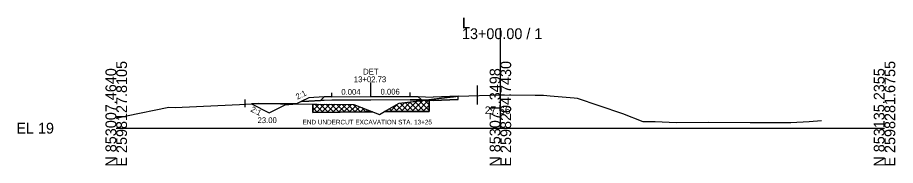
# Model space of a CAD drawing. Extents: x -26 to 1203, y -10 to 9526.
# Drawn here: x -25.7 to 202.8, y 2990.3 to 3028.8 of the extents above; entities that cross this region are included whole.
import ezdxf

# ---------------------------------------------------------------- set-up
doc = ezdxf.new("R2010")
doc.units = 0
for name, color, linetype in [('Exist Cross Section Cell', 7, 'Continuous'), ('Exist XS Center Line Elevation Label', 7, 'Continuous'), ('Exist XS Ground Line', 7, 'Continuous'), ('Prop XS Alignment Label', 7, 'Continuous'), ('Prop XS DDE', 7, 'Continuous'), ('Prop XS DDE Earthwork Shape', 7, 'Continuous'), ('Prop XS DDE Elevations', 7, 'Continuous'), ('Prop XS DDE Slope Text', 7, 'Continuous'), ('Prop XS Earthwork Shape', 7, 'Continuous'), ('Prop XS EOT Tick Mark', 7, 'Continuous'), ('Prop XS Exc Vertical Line 1', 7, 'Continuous'), ('Prop XS Exc Vertical Line 2', 7, 'Continuous'), ('Prop XS Finish Grade', 7, 'Continuous'), ('Prop XS Finish Grade Earthwork', 7, 'Continuous'), ('Prop XS Finish Grade Paved Shoulder', 7, 'Continuous'), ('Prop XS Finish Grade Pavement', 7, 'Continuous'), ('Prop XS Pvmt Edge Slope', 7, 'Continuous'), ('Prop XS SE Text', 7, 'Continuous'), ('Prop XS Side Slope Text', 7, 'Continuous'), ('Prop XS Station Labels', 7, 'Continuous'), ('Prop XS Subgrade Earthwork', 7, 'Continuous'), ('Prop XS Undercut Exc', 7, 'Continuous'), ('Prop XS Undercut Exc Hatch', 7, 'Continuous'), ('Scratch_Level_1', 7, 'Continuous')]:
    doc.layers.add(name, color=color, linetype=linetype)

msp = doc.modelspace()

# ---------------------------------------------------------------- linework, layer by layer
at = {"layer": 'Exist Cross Section Cell'}
for p, q in [((100, 3000), (100, 3025.98)), ((0, 3000), (100, 3000)), ((100, 3000), (200, 3000))]:
    msp.add_line(p, q, dxfattribs=at)
at = {"layer": 'Exist XS Ground Line'}
for p, q in [((73.62, 3006.47), (86.15, 3007.96)), ((86.15, 3007.96), (87.75, 3008.15)), ((87.75, 3008.15), (89.02, 3008.31)), ((89.02, 3008.31), (100.04, 3008.66)), ((100.04, 3008.66), (101.05, 3008.65)), ((101.05, 3008.65), (109.05, 3008.59)), ((109.05, 3008.59), (111.19, 3008.56)), ((111.19, 3008.56), (112.93, 3008.44)), ((112.93, 3008.44), (119.17, 3007.88)), ((119.17, 3007.88), (119.98, 3007.8)), ((119.98, 3007.8), (125.64, 3005.89)), ((2.69, 3003.22), (13.66, 3005.51)), ((13.66, 3005.51), (15.37, 3005.41)), ((15.37, 3005.41), (26.45, 3005.94)), ((26.45, 3005.94), (32.12, 3006.18)), ((32.12, 3006.18), (37.09, 3006.4)), ((37.09, 3006.4), (42.78, 3006.36)), ((42.78, 3006.36), (61.85, 3006.15)), ((61.85, 3006.15), (65.4, 3004.76)), ((69.41, 3004.04), (73.62, 3006.47)), ((125.64, 3005.89), (131.81, 3003.78)), ((0, 3002.63), (2.69, 3003.22)), ((65.4, 3004.76), (68.54, 3003.58)), ((68.54, 3003.58), (69.41, 3004.04)), ((131.81, 3003.78), (137.1, 3001.72)), ((137.1, 3001.72), (140.33, 3001.73)), ((140.33, 3001.73), (145.8, 3001.51)), ((145.8, 3001.51), (154.14, 3001.55)), ((154.14, 3001.55), (164.99, 3001.51)), ((164.99, 3001.51), (175.64, 3001.5)), ((175.64, 3001.5), (180.41, 3001.76)), ((180.41, 3001.76), (183.57, 3002))]:
    msp.add_line(p, q, dxfattribs=at)
at = {"layer": 'Prop XS DDE'}
for p, q in [((35.18, 3006.32), (39.81, 3004)), ((39.81, 3004), (43.94, 3006.06)), ((43.94, 3006.06), (46.94, 3006.31))]:
    msp.add_line(p, q, dxfattribs=at)
at = {"layer": 'Prop XS DDE Earthwork Shape'}
for p, q in [((37.09, 3006.4), (35.18, 3006.32)), ((35.18, 3006.32), (39.81, 3004)), ((42.78, 3006.36), (37.09, 3006.4)), ((39.81, 3004), (43.94, 3006.06)), ((46.94, 3006.31), (42.78, 3006.36)), ((43.94, 3006.06), (46.94, 3006.31))]:
    msp.add_line(p, q, dxfattribs=at)
at = {"layer": 'Prop XS Earthwork Shape'}
for points in [[(81.42, 3007.27), (82.51, 3007.21), (89.02, 3007.45), (89.02, 3008.31), (87.75, 3008.15), (86.15, 3007.96), (80.68, 3007.31)], [(69.87, 3004.3), (73.62, 3006.47), (80.68, 3007.31), (79.42, 3007.37), (78.51, 3007.37), (76.51, 3007.36), (66.3, 3007.29), (56.11, 3007.25), (54.11, 3007.24), (53.19, 3007.24), (50.11, 3007.04), (48.13, 3006.91), (46.94, 3006.31), (51.16, 3006.27), (61.85, 3006.15), (65.4, 3004.76), (66.69, 3004.28), (68.54, 3003.58), (69.41, 3004.04)], [(61.85, 3006.15), (65.4, 3004.76), (66.69, 3004.28), (65.4, 3004.29), (51.16, 3004.11), (51.16, 3006.27)], [(69.87, 3004.3), (73.62, 3006.47), (80.68, 3007.31), (81.42, 3007.27), (81.42, 3004.37), (70.25, 3004.32)]]:
    msp.add_lwpolyline(points, close=True, dxfattribs=at)
at = {"layer": 'Prop XS EOT Tick Mark'}
for p, q in [((56.11, 3008.17), (56.11, 3009.17)), ((76.51, 3008.27), (76.51, 3009.27))]:
    msp.add_line(p, q, dxfattribs=at)
at = {"layer": 'Prop XS Exc Vertical Line 1'}
msp.add_line((33.49, 3007.43), (33.49, 3005.43), dxfattribs=at)
at = {"layer": 'Prop XS Exc Vertical Line 2'}
msp.add_line((93.95, 3011.14), (93.95, 3006.15), dxfattribs=at)
at = {"layer": 'Prop XS Finish Grade'}
for p, q in [((50.11, 3007.9), (48.13, 3006.91)), ((54.11, 3008.16), (50.11, 3007.9)), ((78.51, 3008.28), (82.51, 3008.07)), ((89.02, 3008.31), (82.51, 3008.07))]:
    msp.add_line(p, q, dxfattribs=at)
at = {"layer": 'Prop XS Finish Grade Earthwork'}
msp.add_line((48.13, 3006.91), (46.94, 3006.31), dxfattribs=at)
at = {"layer": 'Prop XS Finish Grade Paved Shoulder'}
for p, q in [((56.11, 3008.17), (54.11, 3008.16)), ((76.51, 3008.27), (78.51, 3008.28))]:
    msp.add_line(p, q, dxfattribs=at)
at = {"layer": 'Prop XS Finish Grade Pavement'}
for p, q in [((56.11, 3008.17), (66.3, 3008.21)), ((66.3, 3008.21), (76.51, 3008.27))]:
    msp.add_line(p, q, dxfattribs=at)
at = {"layer": 'Prop XS Pvmt Edge Slope'}
for p, q in [((54.11, 3008.16), (53.19, 3007.24)), ((78.51, 3008.28), (79.42, 3007.37))]:
    msp.add_line(p, q, dxfattribs=at)
at = {"layer": 'Prop XS Side Slope Text'}
msp.add_line((66.3, 3008.21), (66.3, 3011.86), dxfattribs=at)
at = {"layer": 'Prop XS Subgrade Earthwork'}
for p, q in [((89.02, 3007.45), (89.02, 3008.31)), ((50.11, 3007.04), (48.13, 3006.91)), ((53.19, 3007.24), (50.11, 3007.04)), ((54.11, 3007.24), (53.19, 3007.24)), ((56.11, 3007.25), (54.11, 3007.24)), ((66.3, 3007.29), (56.11, 3007.25)), ((76.51, 3007.36), (66.3, 3007.29)), ((76.51, 3007.36), (78.51, 3007.37)), ((78.51, 3007.37), (79.42, 3007.37)), ((79.42, 3007.37), (82.51, 3007.21)), ((89.02, 3007.45), (82.51, 3007.21))]:
    msp.add_line(p, q, dxfattribs=at)
at = {"layer": 'Prop XS Undercut Exc'}
for p, q in [((51.16, 3006.27), (51.16, 3004.11)), ((81.42, 3004.37), (81.42, 3007.27)), ((51.16, 3004.11), (65.4, 3004.29)), ((65.4, 3004.29), (66.69, 3004.28)), ((69.87, 3004.3), (70.25, 3004.32)), ((70.25, 3004.32), (81.42, 3004.37))]:
    msp.add_line(p, q, dxfattribs=at)
at = {"layer": 'Prop XS Undercut Exc Hatch'}
for p, q in [((51.16, 3006), (51.44, 3006.27)), ((51.16, 3004.58), (52.83, 3006.25)), ((51.16, 3005.37), (52.41, 3004.12)), ((51.68, 3006.26), (53.8, 3004.14)), ((52.11, 3004.12), (54.23, 3006.24)), ((53.11, 3006.25), (55.2, 3004.16)), ((53.55, 3004.14), (55.63, 3006.22)), ((54.54, 3006.23), (56.6, 3004.18)), ((54.98, 3004.15), (57.03, 3006.21)), ((55.97, 3006.22), (57.99, 3004.19)), ((56.41, 3004.17), (58.43, 3006.19)), ((57.4, 3006.2), (59.39, 3004.21)), ((57.85, 3004.19), (59.83, 3006.18)), ((58.83, 3006.19), (60.78, 3004.23)), ((59.28, 3004.21), (61.23, 3006.16)), ((60.26, 3006.17), (62.18, 3004.25)), ((60.71, 3004.23), (62.42, 3005.94)), ((61.69, 3006.16), (63.58, 3004.27)), ((62.14, 3004.25), (63.44, 3005.54)), ((63.89, 3005.36), (64.97, 3004.28)), ((71.3, 3004.32), (73.19, 3006.22)), ((72.03, 3005.55), (73.24, 3004.33)), ((72.72, 3004.33), (75.02, 3006.63)), ((72.93, 3006.06), (74.65, 3004.34)), ((73.9, 3006.5), (76.06, 3004.35)), ((74.14, 3004.34), (76.62, 3006.82)), ((75.17, 3006.65), (77.46, 3004.35)), ((75.56, 3004.34), (78.23, 3007.01)), ((76.43, 3006.8), (78.87, 3004.36)), ((76.98, 3004.35), (79.83, 3007.2)), ((77.7, 3006.95), (80.28, 3004.37)), ((78.4, 3004.36), (81.31, 3007.27)), ((78.96, 3007.1), (81.42, 3004.64)), ((79.82, 3004.37), (81.42, 3005.96)), ((80.23, 3007.25), (81.42, 3006.06)), ((63.58, 3004.27), (64.46, 3005.15)), ((65.01, 3004.29), (65.47, 3004.75)), ((66.21, 3004.46), (66.39, 3004.28)), ((66.42, 3004.28), (66.49, 3004.35)), ((70.23, 3004.51), (70.43, 3004.32)), ((71.13, 3005.03), (71.83, 3004.33)), ((81.24, 3004.37), (81.42, 3004.55))]:
    msp.add_line(p, q, dxfattribs=at)
for points in [[(66.69, 3004.28), (65.4, 3004.29), (51.16, 3004.11), (51.16, 3006.27), (61.85, 3006.15)], [(81.42, 3004.37), (70.25, 3004.32), (69.87, 3004.3), (73.62, 3006.47), (79.61, 3007.18), (80.68, 3007.31), (81.42, 3007.27)]]:
    msp.add_lwpolyline(points, close=True, dxfattribs=at)
at = {"layer": 'Scratch_Level_1'}
msp.add_lwpolyline([(50.11, 3007.9), (48.13, 3006.91), (50.11, 3007.04), (53.19, 3007.24), (54.11, 3008.16)], close=True, dxfattribs=at)

# ---------------------------------------------------------------- texts
at = {"layer": 'Exist Cross Section Cell'}
for s, p in [('L', (90, 3025.98)), ('13+00.00 / 1', (90, 3023.18)), ('EL 19', (-26, 2998.6))]:
    msp.add_text(s, height=2.8, dxfattribs=at).set_placement(p)
for s, p in [('E 2598127.8105', (2.8, 2990)), ('E 2598204.7430', (102.8, 2990)), ('E 2598281.6755', (202.8, 2990)), ('N 853007.4640', (0, 2990)), ('N 853071.3498', (100, 2990)), ('N 853135.2355', (200, 2990))]:
    msp.add_text(s, height=2.8, rotation=90, dxfattribs=at).set_placement(p)
at = {"layer": 'Exist XS Center Line Elevation Label'}
msp.add_text('27.66', height=2, dxfattribs=at).set_placement((95.94, 3003.66))
at = {"layer": 'Prop XS Alignment Label'}
msp.add_text('DET', height=1.5, dxfattribs=at).set_placement((64.27, 3013.96))
at = {"layer": 'Prop XS DDE Elevations'}
msp.add_text('23.00', height=1.5, rotation=360, dxfattribs=at).set_placement((36.78, 3001.32))
at = {"layer": 'Prop XS DDE Slope Text'}
msp.add_text('2:1', height=1.5, rotation=333.4349, dxfattribs=at).set_placement((34.83, 3004.44))
at = {"layer": 'Prop XS SE Text'}
for s, rotation, p in [('0.004', 0.256, (58.59, 3008.68)), ('0.006', 0.3452, (68.8, 3008.73))]:
    msp.add_text(s, height=1.5, rotation=rotation, dxfattribs=at).set_placement(p)
at = {"layer": 'Prop XS Side Slope Text'}
msp.add_text('2:1', height=1.5, rotation=26.5651, dxfattribs=at).set_placement((47.18, 3007.38))
at = {"layer": 'Prop XS Station Labels'}
msp.add_text('13+02.73', height=1.5, dxfattribs=at).set_placement((61.85, 3011.97))
at = {"layer": 'Prop XS Undercut Exc Hatch'}
msp.add_text('END UNDERCUT EXCAVATION STA. 13+25', height=1.2, dxfattribs=at).set_placement((48.52, 3000.98))

doc.saveas('drawing.dxf')
